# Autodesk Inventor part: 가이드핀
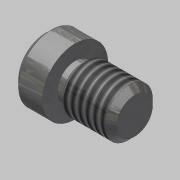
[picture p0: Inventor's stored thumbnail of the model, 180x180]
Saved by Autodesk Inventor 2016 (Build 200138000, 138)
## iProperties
Created: 2019-02
Part Number: 가이드핀
Material: 스테인리스강
Document SubType Name: Modeling
Designer: mduedu
Density: 1 g/cm^3
Appearance: 반광택
Author: mduedu
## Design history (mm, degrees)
sketch "스케치1"
  geometry: C1 r 5.5 at (0, 0); 1 further point
  constraints: 1 centre point, 1 coincident
  dimensions: "d0" = 11 diameter of C1
extrude "돌출1" new body sketch "스케치1" distance "d1" = 5; taper "d2" = 0 deg
sketch "스케치2"
  geometry: C1 r 3 at (0, 0); 1 further point
  constraints: 1 centre point, 1 coincident
  dimensions: "d3" = 6 diameter of C1
extrude "돌출2" join sketch "스케치2" distance "d4" = 1; taper "d5" = 0 deg
sketch "스케치3"
  geometry: C1 r 4 at (0, 0); 1 further point
  constraints: 1 centre point, 1 coincident
  dimensions: "d6" = 8 diameter of C1
extrude "돌출3" join sketch "스케치3" distance "d7" = 9; taper "d8" = 0 deg
chamfer "모따기1" distance "d9" = 1; stored, may be unused: second distance "d10" = 2, angle "d11" = 45 deg
feature "스레드1" dims "d12" = 10, "d13" = 0
node "솔리드1"
